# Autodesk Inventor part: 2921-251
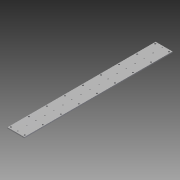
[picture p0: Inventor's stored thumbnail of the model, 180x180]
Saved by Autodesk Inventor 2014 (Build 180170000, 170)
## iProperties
Company: NHTSA/VRTC
Created: 2012-02
Part Number: 2921-251
Project: CHILD SIDE IMPACT SLED
Material: Steel
Description: RAIL MTG. PLATE
Document SubType Name: Sheet Metal
Designer: Mike Vanvoorhis
Mass: 14506.1 g
Surface Area: 4265.56 cm^2
Volume: 1847.91 cm^3
Density: 7.85 g/cm^3
Stock Number: PL 9.5(3/8") x 150.0(5 7/8") x 1314.5(4'-3 3/4")
Sheet Metal Rule: Default
Appearance: Steel
Title: Rail Mounting Plate
Author: Dave Walker
Subject: Child Side Impact Sled
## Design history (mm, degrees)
sketch "Sketch1"
  geometry: L1 (0, 9.525)-(1314.45, 9.525); L2 (1314.45, 9.525)-(1314.45, 0); L3 (1314.45, 0)-(0, 0); L4 (0, 0)-(0, 9.525); L5 (0, 11.43)-(0, -1.905) reference; L6 (-262.89, 0)-(1577.34, 0) reference
  constraints: 8 end point, 2 collinear, 2 parallel, 1 horizontal, 1 perpendicular
  dimensions: "d0" = 9.525 distance of L3.end L1.start; "d1" = 1314.45 distance of L1.start L1.end
extrude "Extrusion1" new body sketch "Sketch1" stored distance "d2" = 150; taper "d3" = 0 deg
sketch "Sketch2"
  geometry: L1 (0, 0)-(0, 150) reference; L2 (-1577.34, 75)-(262.89, 75) reference; 2 further points
  constraints: 1 vertical alignment
  dimensions: "d6" = 123 distance of point (-17.225, 136.5) point (-17.225, 13.5); "d29" = 17.225 distance from line of point (-17.225, 136.5) L1; "d31" = 61.5 distance from line of point (-17.225, 136.5) L2 (= 0.5 x d6)
hole "Hole1" sketch "Sketch2" at (-17.225, 13.5), (-17.225, 136.5) diameter "d7" = 13.4874; stored, may be unused: countersink angle "d11" = 90 deg, drill point angle "d13" = 118 deg; dims "d8" = 6, "d9" = 4, "d10" = 2, "d12" = 8
sketch "Sketch3"
  geometry: L1 (0, 0)-(0, 150) reference; L2 (-1577.34, 75)-(262.89, 75) reference; C1 r 6.744 at (-17.225, 13.5) reference; 1 further point
  constraints: 1 point on line
  dimensions: "d32" = 17.225 distance from line of point (-17.225, 75) L1
hole "Hole2" sketch "Sketch3" at (-17.225, 75) diameter "d18" = 6.647; stored, may be unused: countersink angle "d22" = 90 deg, drill point angle "d24" = 118 deg; dims "d19" = 6, "d20" = 4, "d21" = 2, "d23" = 8
pattern_linear "Rectangular Pattern1" dims "d16" = 160
pattern_linear "Rectangular Pattern2" dims "d27" = 80
body "Solid1"
other parameters: "Thickness" = 0.5, "KFactor" = 4.4, "BendRadius" = 0.5 (= Thickness), "BendReliefWidth" = 0.5 (= Thickness), "BendReliefDepth" = 0.25 (= 0.5 x Thickness), "CornerReliefSize" = 2 (= 4 x Thickness), "SeamGap" = 0.01, "MinimumRemnant" = 1 (= 2 x Thickness), "TransitionRadius" = 0.5 (= BendRadius), "JacobiRadiusSize" = 0.5 (= Thickness), "GapSize" = 0.5 (= Thickness)
